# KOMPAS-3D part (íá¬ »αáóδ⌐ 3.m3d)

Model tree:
1. Эскиз:1
2. Операция выдавливания:1
     Расстояние 1 = 10
3. Скругление:1
     Радиус = 1
4. Скругление:2
     Радиус = 2
5. Эскиз:2
6. Вырезать элемент выдавливания:1
     Расстояние 1 = 0.2
7. Скругление:3
     Радиус = 0.1
8. Эскиз:3
9. Операция выдавливания:2
     Расстояние 1 = 0.5; Расстояние 2 = 4.9
10. Скругление:4
     Радиус = 0.2
11. Эскиз:4
12. Операция выдавливания:3
     Расстояние 1 = 0.5; Расстояние 2 = 4.9

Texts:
  бак правый 3
  Сплав АЛ8  ГОСТ 1583-93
